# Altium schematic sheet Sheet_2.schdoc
size 251 x 191 mm
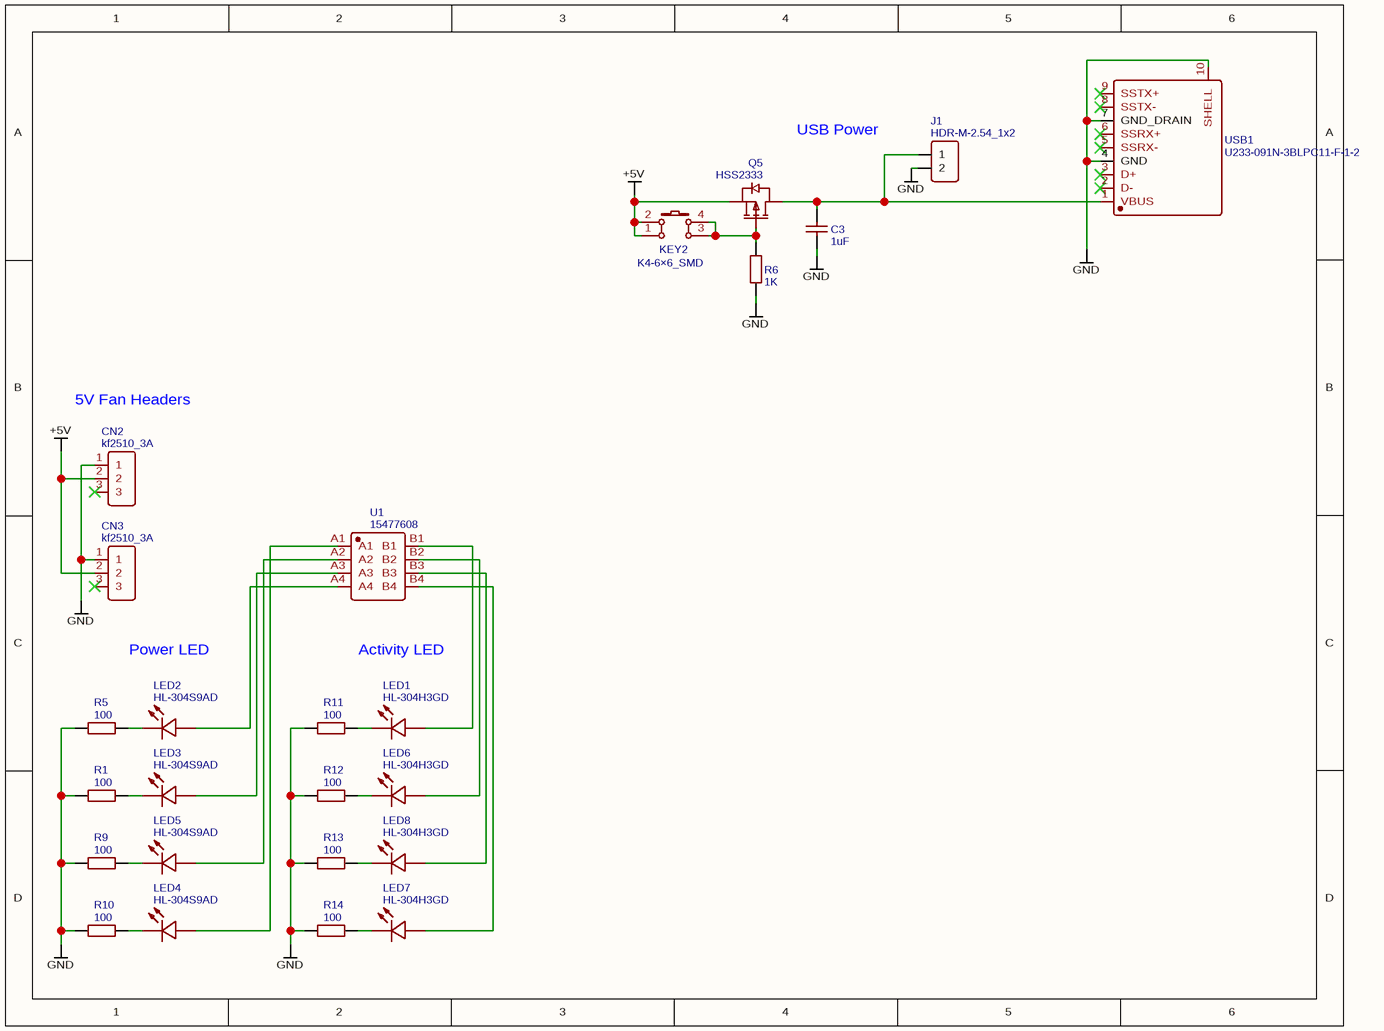
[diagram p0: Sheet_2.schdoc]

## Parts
C3  1uF  [C1206]
CN2  kf2510_3A  [CONN-TH_3P-P2.00_KF2510_3A]
CN3  kf2510_3A  [CONN-TH_3P-P2.00_KF2510_3A]
J1  HDR-M-2.54_1x2  [HDR-M-2.54_1X2]
KEY2  K4-6×6_SMD  [KEY-SMD_4P-L6.0-W6.0-P3.90-LS10.0]
LED1  HL-304H3GD  [LED-TH_BD3.0-P2.54-FD]
LED2  HL-304S9AD  [LED-TH_BD3.0-P2.54-FD]
LED3  HL-304S9AD  [LED-TH_BD3.0-P2.54-FD]
LED4  HL-304S9AD  [LED-TH_BD3.0-P2.54-FD]
LED5  HL-304S9AD  [LED-TH_BD3.0-P2.54-FD]
LED6  HL-304H3GD  [LED-TH_BD3.0-P2.54-FD]
LED7  HL-304H3GD  [LED-TH_BD3.0-P2.54-FD]
LED8  HL-304H3GD  [LED-TH_BD3.0-P2.54-FD]
Q5  HSS2333  [SOT-23-3_L2.9-W1.3-P1.90-LS2.4-BR]
R1  100  [R1206]
R5  100  [R1206]
R6  1K  [R1206]
R9  100  [R1206]
R10  100  [R1206]
R11  100  [R1206]
R12  100  [R1206]
R13  100  [R1206]
R14  100  [R1206]
U1  15477608  [CONN-TH_8P-P2.54-V-M_15477608]
USB1  U233-091N-3BLPC11-F-1-2  [USB3.0-A-TH_U233-091N-1BLPC15-S-1-2]

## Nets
+5V: CN2.2 CN3.2 KEY2.1 KEY2.2 Q5.2(S)
GND: C3.1 CN2.1 CN3.1 J1.2 R1.1 R5.1 R6.1 R9.1 R10.1 R11.1 R12.1 R13.1 R14.1 USB1.4(GND) USB1.7(GND_DRAIN) USB1.10(SHELL)
NetC3_2: C3.2 J1.1 Q5.3(D) USB1.1(VBUS)
NetKEY2_3: KEY2.3 KEY2.4 Q5.1(G) R6.2
NetLED1_1: LED1.1(C) R11.2
NetLED1_2: LED1.2(A) U1.B1
NetLED2_1: LED2.1(C) R5.2
NetLED2_2: LED2.2(A) U1.A4
NetLED3_1: LED3.1(C) R1.2
NetLED3_2: LED3.2(A) U1.A3
NetLED4_1: LED4.1(C) R10.2
NetLED4_2: LED4.2(A) U1.A1
NetLED5_1: LED5.1(C) R9.2
NetLED5_2: LED5.2(A) U1.A2
NetLED6_1: LED6.1(C) R12.2
NetLED6_2: LED6.2(A) U1.B2
NetLED7_1: LED7.1(C) R14.2
NetLED7_2: LED7.2(A) U1.B4
NetLED8_1: LED8.1(C) R13.2
NetLED8_2: LED8.2(A) U1.B3

Not connected (* = marked no-connect by the designer): CN2 3*; CN3 3*; USB1 2(D-)* 3(D+)* 5(SSRX-)* 6(SSRX+)* 8(SSTX-)* 9(SSTX+)*

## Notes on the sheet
- USB Power
- 5V Fan Headers
- Power LED
- Activity LED

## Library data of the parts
C3 = 1uF: BOM_Manufacturer: YAGEO; BOM_Manufacturer Part: CC1206KKX7R8BB105; nameAlias: Capacitance; SMT Type: Extend; BOM_Paste Type: expand
CN2 CN3 = kf2510_3A: BOM_Manufacturer: BOOMELE; SMT Type: Extend; BOM_Paste Type: expand
J1 = HDR-M-2.54_1x2: Contributor: LCEDA_Lib
KEY2 = K4-6×6_SMD: BOM_Manufacturer: 韩国韩荣; BOM_Manufacturer Part: K2-6639SP-D4SC-04; Contributor: LCEDA_Lib
LED1 LED6-LED8 = HL-304H3GD: BOM_Manufacturer: HONGLITRONIC(Hongli Zhihui (HONGLITRONIC)); Contributor: LCSC; SMT Type: Extend; BOM_Paste Type: expand
LED2-LED5 = HL-304S9AD: BOM_Manufacturer: HONGLITRONIC(Hongli Zhihui (HONGLITRONIC)); Contributor: LCSC; SMT Type: Extend; BOM_Paste Type: expand
Q5 = HSS2333: BOM_Manufacturer: HUASHUO; Contributor: LCSC
R1 R5 R9-R14 = 100: BOM_Manufacturer: YAGEO; BOM_Manufacturer Part: RC1206JR-07100RL; nameAlias: Resistance (Ohms); Contributor: LCSC
R6 = 1K: BOM_Manufacturer: YAGEO; BOM_Manufacturer Part: RC1206FR-071KL; nameAlias: Resistance (Ohms)
U1 = 15477608: BOM_Manufacturer: MOLEX; Contributor: LCSC; SMT Type: Extend; BOM_Paste Type: expand
USB1 = U233-091N-3BLPC11-F-1-2: BOM_Manufacturer: XKB Enterprise; Contributor: LCSC; SMT Type: Extend; BOM_Paste Type: expand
